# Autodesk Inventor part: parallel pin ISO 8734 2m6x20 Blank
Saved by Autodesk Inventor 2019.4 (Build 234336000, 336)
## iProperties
Created: 2021-08
Part Number: parallel pin ISO 8734 2m6x20 Blank
Material: Generic
Document SubType Name: Modeling
Designer: Administrator
Density: 1 g/cm^3
Appearance: Default
Title: parallel pin ISO 8734 2m6x20 Blank
Author: Administrator
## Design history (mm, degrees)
feature "Body1"
body "Solid1"
